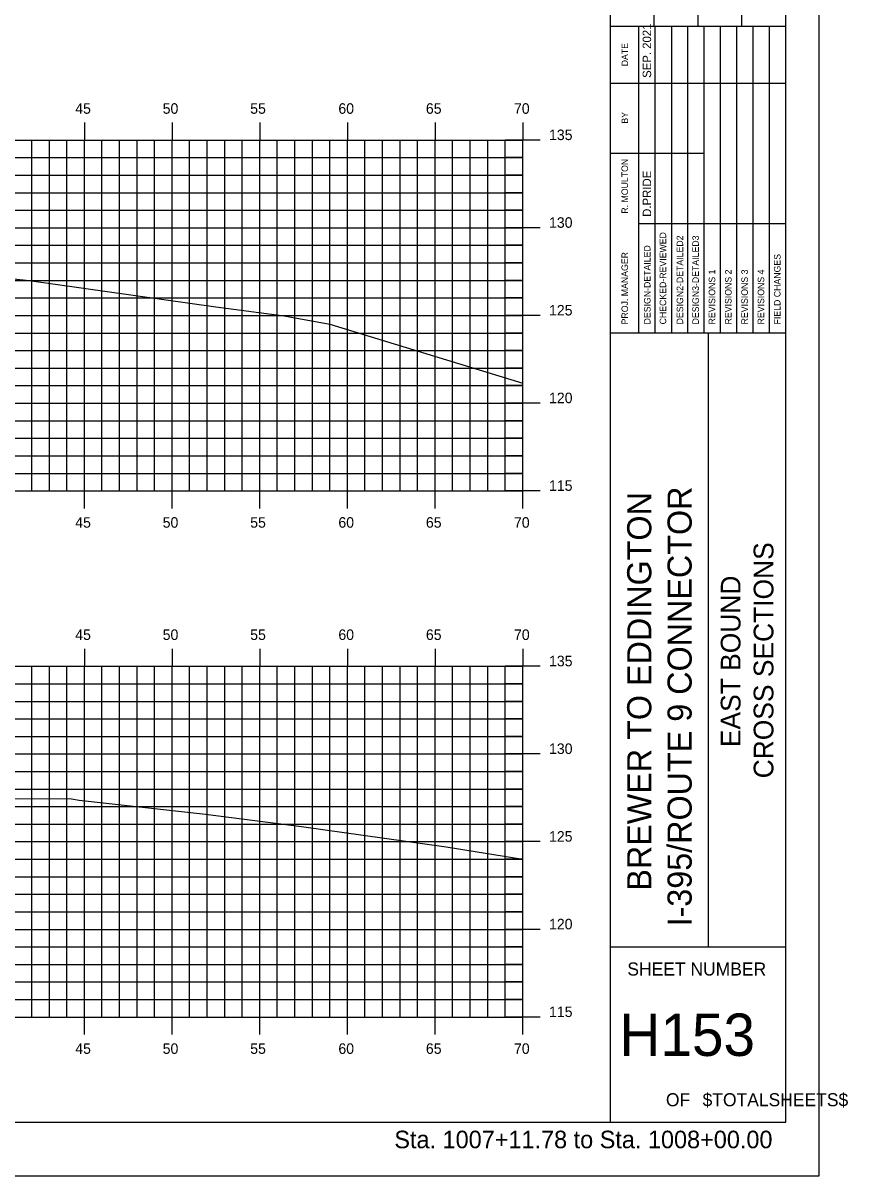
# Model space of a CAD drawing. Extents: x 851738 to 851910, y 365624 to 365734.
# Drawn here: x 851863 to 851910.1, y 365624 to 365689.7 of the extents above; entities that cross this region are included whole.
import ezdxf

# ---------------------------------------------------------------- set-up
doc = ezdxf.new("R2010")
doc.units = 0
for name, color, linetype in [('BORDER', 7, 'Continuous'), ('H_V ANNOTATION', 7, 'Continuous'), ('MAJOR', 7, 'Continuous'), ('MINOR', 7, 'Continuous'), ('PLOT BOUNDARY', 7, 'Continuous'), ('S_Roadway_Centerline', 7, 'Continuous')]:
    doc.layers.add(name, color=color, linetype=linetype)

msp = doc.modelspace()

# ---------------------------------------------------------------- linework, layer by layer
at = {"layer": 'BORDER'}
for p, q in [((851896.522, 365627.027), (851896.522, 365732.027)), ((851899.022, 365689.53), (851899.022, 365698.177)), ((851901.522, 365689.53), (851901.522, 365698.177)), ((851904.022, 365689.53), (851904.022, 365698.177)), ((851896.522, 365689.53), (851906.522, 365689.53)), ((851896.522, 365672.03), (851906.522, 365672.03)), ((851902.113, 365637.03), (851902.113, 365672.03)), ((851896.522, 365637.03), (851906.522, 365637.03))]:
    msp.add_line(p, q, dxfattribs=at)
msp.add_lwpolyline([(851746.522, 365627.027), (851906.522, 365627.027), (851906.522, 365732.027), (851746.522, 365732.027)], close=True, dxfattribs=at)
for points in [[(851898.137, 365686.28), (851898.137, 365689.53)], [(851899.07, 365672.033), (851899.07, 365689.53)], [(851900.002, 365689.53), (851900.002, 365672.033)], [(851900.933, 365672.033), (851900.933, 365689.53)], [(851901.865, 365672.033), (851901.865, 365689.53)], [(851902.797, 365672.033), (851902.797, 365689.53)], [(851903.728, 365672.033), (851903.728, 365689.53)], [(851904.66, 365672.033), (851904.66, 365689.53)], [(851905.592, 365672.033), (851905.592, 365689.53)], [(851898.138, 365672.033), (851898.138, 365688.824)], [(851896.522, 365686.28), (851906.522, 365686.28)], [(851896.522, 365682.28), (851898.138, 365682.28)], [(851898.137, 365682.28), (851901.864, 365682.28)], [(851898.137, 365678.28), (851906.522, 365678.28)]]:
    msp.add_lwpolyline(points, dxfattribs=at)
at = {"layer": 'MAJOR'}
for p, q in [((851866.522, 365684.029), (851866.522, 365683.027)), ((851871.522, 365684.029), (851871.522, 365683.027)), ((851876.522, 365684.029), (851876.522, 365683.027)), ((851881.522, 365684.029), (851881.522, 365683.027)), ((851886.522, 365684.029), (851886.522, 365683.027)), ((851891.522, 365684.029), (851891.522, 365683.027)), ((851751.522, 365683.027), (851891.522, 365683.027)), ((851751.522, 365683.027), (851891.522, 365683.027)), ((851866.522, 365663.027), (851866.522, 365683.027)), ((851871.522, 365663.027), (851871.522, 365683.027)), ((851876.522, 365663.027), (851876.522, 365683.027)), ((851881.522, 365663.027), (851881.522, 365683.027)), ((851886.522, 365663.027), (851886.522, 365683.027)), ((851892.524, 365683.027), (851890.52, 365683.027)), ((851891.522, 365663.027), (851891.522, 365683.027)), ((851891.522, 365663.027), (851891.522, 365683.027)), ((851751.522, 365678.027), (851891.522, 365678.027)), ((851892.524, 365678.027), (851890.52, 365678.027)), ((851751.522, 365673.027), (851891.522, 365673.027)), ((851892.524, 365673.027), (851890.52, 365673.027)), ((851751.522, 365668.027), (851891.522, 365668.027)), ((851892.524, 365668.027), (851890.52, 365668.027)), ((851751.522, 365663.027), (851891.522, 365663.027)), ((851751.522, 365663.027), (851891.522, 365663.027)), ((851866.522, 365662.025), (851866.522, 365663.027)), ((851871.522, 365662.025), (851871.522, 365663.027)), ((851876.522, 365662.025), (851876.522, 365663.027)), ((851881.522, 365662.025), (851881.522, 365663.027)), ((851886.522, 365662.025), (851886.522, 365663.027)), ((851892.524, 365663.027), (851890.52, 365663.027)), ((851891.522, 365662.025), (851891.522, 365663.027)), ((851866.522, 365654.029), (851866.522, 365653.027)), ((851871.522, 365654.029), (851871.522, 365653.027)), ((851876.522, 365654.029), (851876.522, 365653.027)), ((851881.522, 365654.029), (851881.522, 365653.027)), ((851886.522, 365654.029), (851886.522, 365653.027)), ((851891.522, 365654.029), (851891.522, 365653.027)), ((851751.522, 365653.027), (851891.522, 365653.027)), ((851751.522, 365653.027), (851891.522, 365653.027)), ((851866.522, 365633.027), (851866.522, 365653.027)), ((851871.522, 365633.027), (851871.522, 365653.027)), ((851876.522, 365633.027), (851876.522, 365653.027)), ((851881.522, 365633.027), (851881.522, 365653.027)), ((851886.522, 365633.027), (851886.522, 365653.027)), ((851892.524, 365653.027), (851890.52, 365653.027)), ((851891.522, 365633.027), (851891.522, 365653.027)), ((851891.522, 365633.027), (851891.522, 365653.027)), ((851751.522, 365648.027), (851891.522, 365648.027)), ((851892.524, 365648.027), (851890.52, 365648.027)), ((851751.522, 365643.027), (851891.522, 365643.027)), ((851892.524, 365643.027), (851890.52, 365643.027)), ((851751.522, 365638.027), (851891.522, 365638.027)), ((851892.524, 365638.027), (851890.52, 365638.027)), ((851751.522, 365633.027), (851891.522, 365633.027)), ((851751.522, 365633.027), (851891.522, 365633.027)), ((851866.522, 365632.025), (851866.522, 365633.027)), ((851871.522, 365632.025), (851871.522, 365633.027)), ((851876.522, 365632.025), (851876.522, 365633.027)), ((851881.522, 365632.025), (851881.522, 365633.027)), ((851886.522, 365632.025), (851886.522, 365633.027)), ((851892.524, 365633.027), (851890.52, 365633.027)), ((851891.522, 365632.025), (851891.522, 365633.027))]:
    msp.add_line(p, q, dxfattribs=at)
at = {"layer": 'MINOR'}
for p, q in [((851863.522, 365663.027), (851863.522, 365683.027)), ((851864.522, 365663.027), (851864.522, 365683.027)), ((851865.522, 365663.027), (851865.522, 365683.027)), ((851867.522, 365663.027), (851867.522, 365683.027)), ((851868.522, 365663.027), (851868.522, 365683.027)), ((851869.522, 365663.027), (851869.522, 365683.027)), ((851870.522, 365663.027), (851870.522, 365683.027)), ((851872.522, 365663.027), (851872.522, 365683.027)), ((851873.522, 365663.027), (851873.522, 365683.027)), ((851874.522, 365663.027), (851874.522, 365683.027)), ((851875.522, 365663.027), (851875.522, 365683.027)), ((851877.522, 365663.027), (851877.522, 365683.027)), ((851878.522, 365663.027), (851878.522, 365683.027)), ((851879.522, 365663.027), (851879.522, 365683.027)), ((851880.522, 365663.027), (851880.522, 365683.027)), ((851882.522, 365663.027), (851882.522, 365683.027)), ((851883.522, 365663.027), (851883.522, 365683.027)), ((851884.522, 365663.027), (851884.522, 365683.027)), ((851885.522, 365663.027), (851885.522, 365683.027)), ((851887.522, 365663.027), (851887.522, 365683.027)), ((851888.522, 365663.027), (851888.522, 365683.027)), ((851889.522, 365663.027), (851889.522, 365683.027)), ((851890.522, 365663.027), (851890.522, 365683.027)), ((851751.522, 365682.027), (851891.522, 365682.027)), ((851891.522, 365682.027), (851890.52, 365682.027)), ((851751.522, 365681.027), (851891.522, 365681.027)), ((851891.522, 365681.027), (851890.52, 365681.027)), ((851751.522, 365680.027), (851891.522, 365680.027)), ((851891.522, 365680.027), (851890.52, 365680.027)), ((851751.522, 365679.027), (851891.522, 365679.027)), ((851891.522, 365679.027), (851890.52, 365679.027)), ((851751.522, 365677.027), (851891.522, 365677.027)), ((851891.522, 365677.027), (851890.52, 365677.027)), ((851751.522, 365676.027), (851891.522, 365676.027)), ((851891.522, 365676.027), (851890.52, 365676.027)), ((851751.522, 365675.027), (851891.522, 365675.027)), ((851891.522, 365675.027), (851890.52, 365675.027)), ((851751.522, 365674.027), (851891.522, 365674.027)), ((851891.522, 365674.027), (851890.52, 365674.027)), ((851751.522, 365672.027), (851891.522, 365672.027)), ((851891.522, 365672.027), (851890.52, 365672.027)), ((851751.522, 365671.027), (851891.522, 365671.027)), ((851891.522, 365671.027), (851890.52, 365671.027)), ((851751.522, 365670.027), (851891.522, 365670.027)), ((851891.522, 365670.027), (851890.52, 365670.027)), ((851751.522, 365669.027), (851891.522, 365669.027)), ((851891.522, 365669.027), (851890.52, 365669.027)), ((851751.522, 365667.027), (851891.522, 365667.027)), ((851891.522, 365667.027), (851890.52, 365667.027)), ((851751.522, 365666.027), (851891.522, 365666.027)), ((851891.522, 365666.027), (851890.52, 365666.027)), ((851751.522, 365665.027), (851891.522, 365665.027)), ((851891.522, 365665.027), (851890.52, 365665.027)), ((851751.522, 365664.027), (851891.522, 365664.027)), ((851891.522, 365664.027), (851890.52, 365664.027)), ((851863.522, 365633.027), (851863.522, 365653.027)), ((851864.522, 365633.027), (851864.522, 365653.027)), ((851865.522, 365633.027), (851865.522, 365653.027)), ((851867.522, 365633.027), (851867.522, 365653.027)), ((851868.522, 365633.027), (851868.522, 365653.027)), ((851869.522, 365633.027), (851869.522, 365653.027)), ((851870.522, 365633.027), (851870.522, 365653.027)), ((851872.522, 365633.027), (851872.522, 365653.027)), ((851873.522, 365633.027), (851873.522, 365653.027)), ((851874.522, 365633.027), (851874.522, 365653.027)), ((851875.522, 365633.027), (851875.522, 365653.027)), ((851877.522, 365633.027), (851877.522, 365653.027)), ((851878.522, 365633.027), (851878.522, 365653.027)), ((851879.522, 365633.027), (851879.522, 365653.027)), ((851880.522, 365633.027), (851880.522, 365653.027)), ((851882.522, 365633.027), (851882.522, 365653.027)), ((851883.522, 365633.027), (851883.522, 365653.027)), ((851884.522, 365633.027), (851884.522, 365653.027)), ((851885.522, 365633.027), (851885.522, 365653.027)), ((851887.522, 365633.027), (851887.522, 365653.027)), ((851888.522, 365633.027), (851888.522, 365653.027)), ((851889.522, 365633.027), (851889.522, 365653.027)), ((851890.522, 365633.027), (851890.522, 365653.027)), ((851751.522, 365652.027), (851891.522, 365652.027)), ((851891.522, 365652.027), (851890.52, 365652.027)), ((851751.522, 365651.027), (851891.522, 365651.027)), ((851891.522, 365651.027), (851890.52, 365651.027)), ((851751.522, 365650.027), (851891.522, 365650.027)), ((851891.522, 365650.027), (851890.52, 365650.027)), ((851751.522, 365649.027), (851891.522, 365649.027)), ((851891.522, 365649.027), (851890.52, 365649.027)), ((851751.522, 365647.027), (851891.522, 365647.027)), ((851891.522, 365647.027), (851890.52, 365647.027)), ((851751.522, 365646.027), (851891.522, 365646.027)), ((851891.522, 365646.027), (851890.52, 365646.027)), ((851751.522, 365645.027), (851891.522, 365645.027)), ((851891.522, 365645.027), (851890.52, 365645.027)), ((851751.522, 365644.027), (851891.522, 365644.027)), ((851891.522, 365644.027), (851890.52, 365644.027)), ((851751.522, 365642.027), (851891.522, 365642.027)), ((851891.522, 365642.027), (851890.52, 365642.027)), ((851751.522, 365641.027), (851891.522, 365641.027)), ((851891.522, 365641.027), (851890.52, 365641.027)), ((851751.522, 365640.027), (851891.522, 365640.027)), ((851891.522, 365640.027), (851890.52, 365640.027)), ((851751.522, 365639.027), (851891.522, 365639.027)), ((851891.522, 365639.027), (851890.52, 365639.027)), ((851751.522, 365637.027), (851891.522, 365637.027)), ((851891.522, 365637.027), (851890.52, 365637.027)), ((851751.522, 365636.027), (851891.522, 365636.027)), ((851891.522, 365636.027), (851890.52, 365636.027)), ((851751.522, 365635.027), (851891.522, 365635.027)), ((851891.522, 365635.027), (851890.52, 365635.027)), ((851751.522, 365634.027), (851891.522, 365634.027)), ((851891.522, 365634.027), (851890.52, 365634.027))]:
    msp.add_line(p, q, dxfattribs=at)
at = {"layer": 'PLOT BOUNDARY'}
msp.add_lwpolyline([(851738.429, 365623.968), (851908.429, 365623.968), (851908.429, 365733.968), (851738.429, 365733.968)], close=True, dxfattribs=at)
at = {"layer": 'S_Roadway_Centerline'}
for points in [[(851811.196, 365672.193), (851820.737, 365673.799), (851824.488, 365674.319), (851827.622, 365674.443), (851841.542, 365675.033), (851841.601, 365675.033), (851841.604, 365675.035), (851841.621, 365675.036), (851853.529, 365675.409), (851857.354, 365675.261), (851861.611, 365675.209), (851863.374, 365675.015), (851874.012, 365673.524), (851877.919, 365672.999), (851880.529, 365672.534), (851891.522, 365669.169)], [(851815.305, 365643.654), (851816.061, 365643.732), (851818.751, 365644.002), (851823.874, 365644.532), (851825.943, 365644.611), (851829.955, 365644.773), (851834.139, 365644.987), (851841.516, 365645.299), (851842.856, 365645.354), (851846.07, 365645.415), (851852.342, 365645.492), (851865.787, 365645.478), (851866.215, 365645.397), (851873.421, 365644.59), (851878.907, 365643.882), (851887.151, 365642.728), (851891.522, 365642.031)]]:
    msp.add_lwpolyline(points, dxfattribs=at)

# ---------------------------------------------------------------- texts
at = {"layer": 'BORDER'}
for s, height, p in [('SEP. 2021', 0.4845, (851898.845, 365686.575)), ('DATE', 0.3714, (851897.527, 365687.235)), ('BY', 0.3714, (851897.527, 365683.965)), ('R. MOULTON', 0.3727, (851897.526, 365678.832)), ('D.PRIDE', 0.4845, (851898.845, 365678.653)), ('CHECKED-REVIEWED', 0.37275, (851899.703, 365672.518)), ('DESIGN2-DETAILED2', 0.37275, (851900.672, 365672.518)), ('DESIGN3-DETAILED3', 0.37275, (851901.567, 365672.518)), ('DESIGN-DETAILED', 0.37275, (851898.809, 365672.518)), ('PROJ. MANAGER', 0.37275, (851897.527, 365672.518)), ('FIELD CHANGES', 0.37275, (851906.225, 365672.518)), ('REVISIONS 1', 0.37275, (851902.498, 365672.518)), ('REVISIONS 2', 0.37275, (851903.43, 365672.518)), ('REVISIONS 3', 0.37275, (851904.362, 365672.518)), ('REVISIONS 4', 0.37275, (851905.293, 365672.518)), ('I-395/ROUTE 9 CONNECTOR', 1.37787, (851901.157, 365638.192)), ('BREWER TO EDDINGTON', 1.37787, (851898.856, 365640.231)), ('CROSS SECTIONS', 1.125, (851905.82, 365646.638)), ('EAST BOUND', 1.125, (851903.941, 365648.418))]:
    msp.add_text(s, height=height, rotation=90, dxfattribs=at).set_placement(p)
for s, height, p in [('SHEET NUMBER', 0.74527, (851897.488, 365635.393)), ('H153', 2.4194, (851897.038, 365630.809)), ('$TOTALSHEETS$', 0.74527, (851901.779, 365627.94)), ('OF', 0.7453, (851899.689, 365627.94))]:
    msp.add_text(s, height=height, dxfattribs=at).set_placement(p)
at = {"layer": 'H_V ANNOTATION'}
for s, height, p in [('45', 0.6, (851866, 365684.527)), ('50', 0.6, (851870.987, 365684.527)), ('55', 0.6, (851875.979, 365684.527)), ('60', 0.6, (851881.008, 365684.527)), ('65', 0.6, (851886, 365684.527)), ('70', 0.6, (851891.024, 365684.527)), ('135', 0.6, (851893.022, 365683.027)), ('130', 0.6, (851893.022, 365678.027)), ('125', 0.6, (851893.022, 365673.027)), ('120', 0.6, (851893.022, 365668.027)), ('115', 0.6, (851893.022, 365663.027)), ('45', 0.6, (851866, 365660.927)), ('50', 0.6, (851870.987, 365660.927)), ('55', 0.6, (851875.979, 365660.927)), ('60', 0.6, (851881.008, 365660.927)), ('65', 0.6, (851886, 365660.927)), ('70', 0.6, (851891.024, 365660.927)), ('45', 0.6, (851866, 365654.527)), ('50', 0.6, (851870.987, 365654.527)), ('55', 0.6, (851875.979, 365654.527)), ('60', 0.6, (851881.008, 365654.527)), ('65', 0.6, (851886, 365654.527)), ('70', 0.6, (851891.024, 365654.527)), ('135', 0.6, (851893.022, 365653.027)), ('130', 0.6, (851893.022, 365648.027)), ('125', 0.6, (851893.022, 365643.027)), ('120', 0.6, (851893.022, 365638.027)), ('115', 0.6, (851893.022, 365633.027)), ('45', 0.6, (851866, 365630.927)), ('50', 0.6, (851870.987, 365630.927)), ('55', 0.6, (851875.979, 365630.927)), ('60', 0.6, (851881.008, 365630.927)), ('65', 0.6, (851886, 365630.927)), ('70', 0.6, (851891.024, 365630.927)), ('Sta. 1007+11.78 to Sta. 1008+00.00', 1.0002, (851884.199, 365625.547))]:
    msp.add_text(s, height=height, dxfattribs=at).set_placement(p)

doc.saveas('drawing.dxf')
